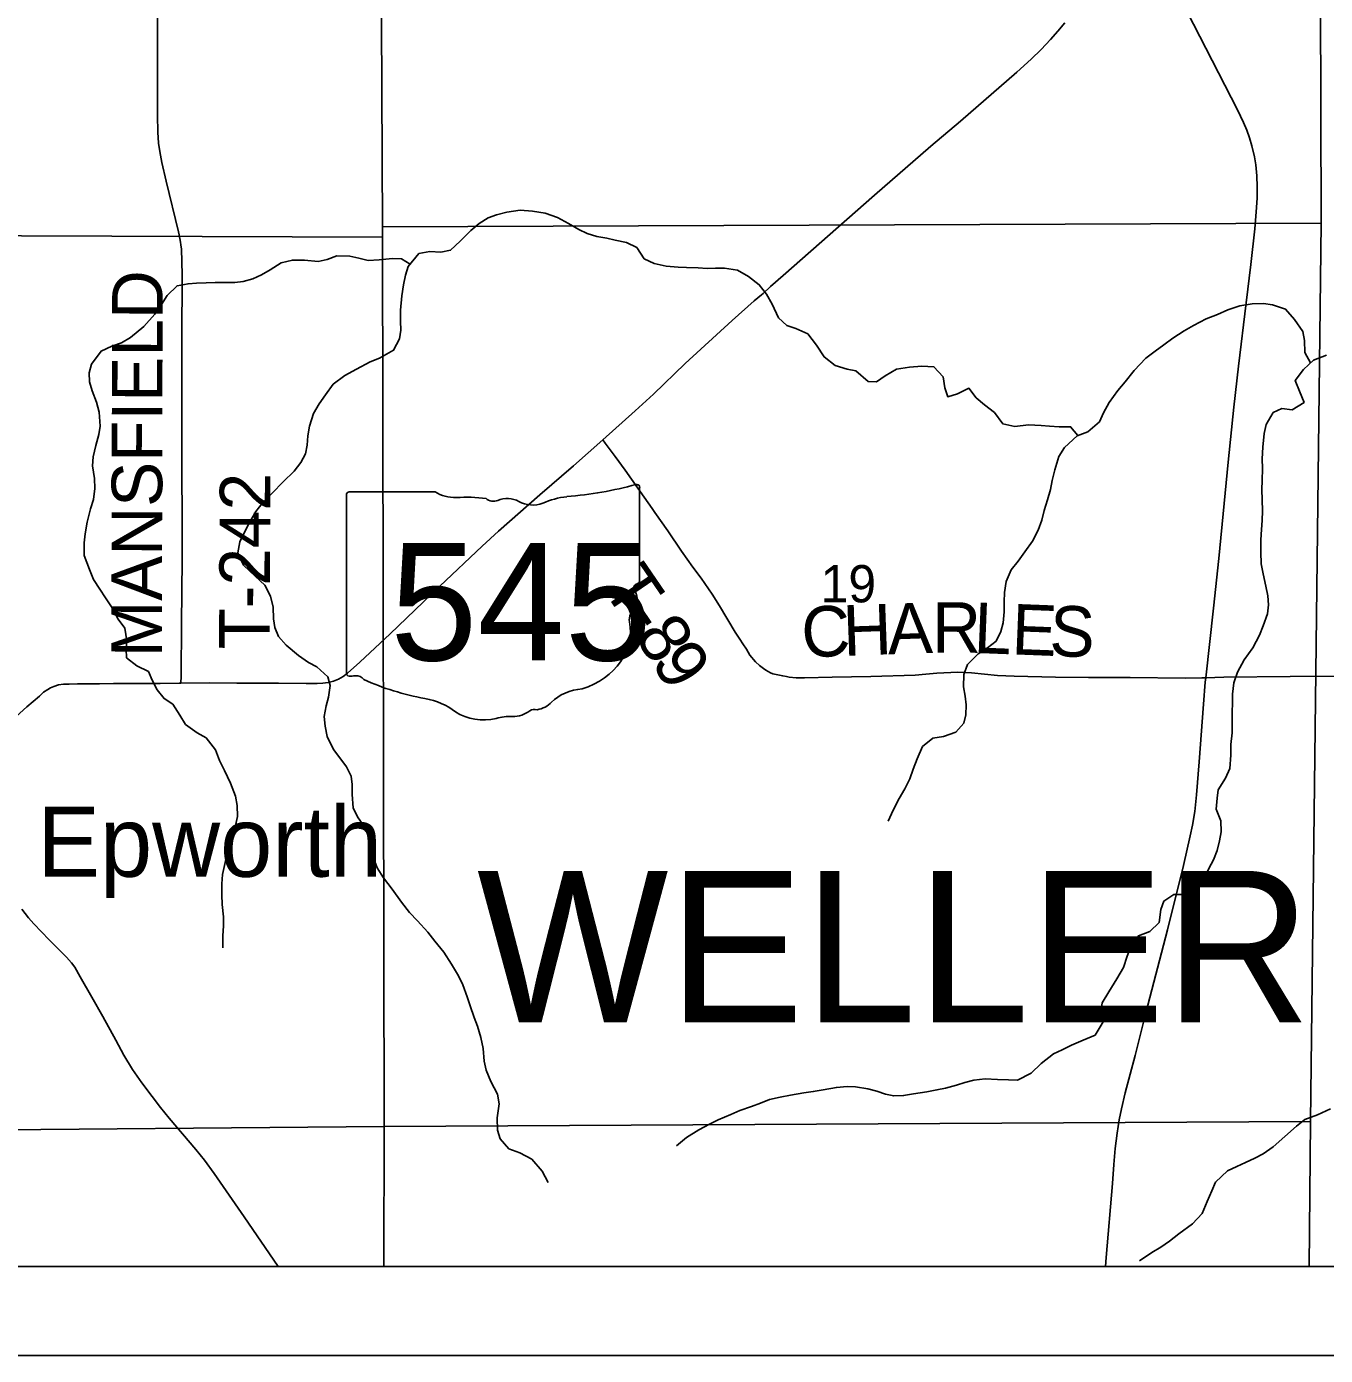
# Model space of a CAD drawing. Extents: x 0 to 34, y 0 to 22.
# Drawn here: x 5.038 to 6.497, y 14 to 15.494 of the extents above; entities that cross this region are included whole.
import ezdxf

# ---------------------------------------------------------------- set-up
doc = ezdxf.new("R2010")
doc.units = 0
for name, color, linetype in [('Default', 7, 'Continuous'), ('GM_X_County_Road', 7, 'Continuous'), ('GM_X_Minor_River', 7, 'Continuous'), ('GM_X_Section', 7, 'Continuous'), ('GM_X_Section_Text', 7, 'Continuous'), ('GM_X_State_Location', 7, 'Continuous'), ('GM_X_State_Route', 7, 'Continuous'), ('GM_X_State_Shield', 7, 'Continuous'), ('GM_X_Township_Road', 7, 'Continuous'), ('GM_X_Township_Road_Text', 7, 'Continuous'), ('GM_X_Township_Text', 7, 'Continuous'), ('GM_X_Unincorporated_Text', 7, 'Continuous'), ('SH_Cut_Line', 7, 'Continuous'), ('SH_Data', 7, 'Continuous')]:
    doc.layers.add(name, color=color, linetype=linetype)

msp = doc.modelspace()

# ---------------------------------------------------------------- linework, layer by layer
at = {"layer": 'Default'}
for points in [[(4.4126, 14.1), (5.4393, 14.1), (5.4396, 14.2573), (4.4107, 14.2482)], [(5.4393, 14.1), (6.4792, 14.1), (6.4806, 14.263), (5.4396, 14.2573)]]:
    msp.add_lwpolyline(points, close=True, dxfattribs=at)
msp.add_lwpolyline([(3.4093, 14.1), (7.4893, 14.1)], dxfattribs=at)
at = {"layer": 'GM_X_County_Road'}
for points in [[(6.363, 14.7617), (6.3718, 14.8401), (6.3776, 14.8957), (6.3836, 14.9576), (6.3883, 15.0039), (6.3946, 15.0658), (6.3996, 15.1121), (6.4083, 15.183), (6.4137, 15.2261), (6.4181, 15.2664), (6.4198, 15.2853), (6.4206, 15.301), (6.4207, 15.3135), (6.4202, 15.3259), (6.4191, 15.3382), (6.4177, 15.3474), (6.4149, 15.3596), (6.4122, 15.3685), (6.4091, 15.3774), (6.4055, 15.386), (6.3988, 15.4001), (6.3846, 15.4277), (6.3348, 15.5244)], [(6.2505, 14.1), (6.2511, 14.1102), (6.2581, 14.1931), (6.2598, 14.2146), (6.2613, 14.2324), (6.2634, 14.2499), (6.2658, 14.2649), (6.2682, 14.277), (6.2724, 14.2951), (6.2835, 14.337), (6.2958, 14.3852), (6.3201, 14.4783), (6.3378, 14.5505), (6.3456, 14.584), (6.348, 14.5961), (6.3506, 14.6114), (6.3527, 14.63), (6.3557, 14.6671), (6.3605, 14.7321), (6.3624, 14.7568), (6.363, 14.7617)]]:
    msp.add_lwpolyline(points, dxfattribs=at)
at = {"layer": 'GM_X_Minor_River'}
for points in [[(6.2193, 15.0339), (6.211, 15.0439), (6.1981, 15.0439), (6.1875, 15.0446), (6.1781, 15.0454), (6.1637, 15.0461), (6.1485, 15.0442), (6.1348, 15.0473), (6.1254, 15.0598), (6.1144, 15.0685), (6.1049, 15.0765), (6.0969, 15.0871), (6.0841, 15.081), (6.0731, 15.0776), (6.0697, 15.0875), (6.0678, 15.1), (6.0575, 15.1114), (6.0439, 15.1121), (6.0299, 15.111), (6.0155, 15.1087), (6.0026, 15.1011), (5.9931, 15.0943), (5.9836, 15.0947), (5.9696, 15.1068), (5.9601, 15.1087), (5.9465, 15.1129), (5.934, 15.1224), (5.9256, 15.1356), (5.9158, 15.1485), (5.9025, 15.1542), (5.8923, 15.1576), (5.8828, 15.1664), (5.8756, 15.1815), (5.8692, 15.1929), (5.8612, 15.2035), (5.8491, 15.2126), (5.8366, 15.2198), (5.8222, 15.2221), (5.8119, 15.2221), (5.8025, 15.2217), (5.7926, 15.2225), (5.7793, 15.2229), (5.7699, 15.2232), (5.7566, 15.2244), (5.7433, 15.2274), (5.7319, 15.2327), (5.7236, 15.2452), (5.7119, 15.2509), (5.6994, 15.2536), (5.6899, 15.2558), (5.6785, 15.2577), (5.6679, 15.2612), (5.6584, 15.2657), (5.647, 15.2725), (5.6345, 15.279), (5.6205, 15.2839), (5.6065, 15.2862), (5.5925, 15.2873), (5.5777, 15.285), (5.5659, 15.282), (5.5565, 15.2786), (5.5466, 15.2725), (5.5371, 15.2646), (5.525, 15.2524), (5.5144, 15.2422), (5.5034, 15.2403), (5.4912, 15.241), (5.4787, 15.2388), (5.4666, 15.224), (5.4635, 15.2141), (5.4613, 15.2035), (5.4594, 15.191), (5.4582, 15.175), (5.4582, 15.1625), (5.4586, 15.1523), (5.4571, 15.1428), (5.4502, 15.1299), (5.4343, 15.1208), (5.4241, 15.117), (5.4085, 15.1086), (5.3956, 15.1014), (5.3824, 15.0916), (5.3736, 15.0798), (5.3668, 15.0696), (5.3603, 15.0586), (5.3558, 15.0445), (5.3539, 15.0335), (5.3531, 15.0233), (5.3512, 15.0134), (5.3459, 15.0036), (5.3387, 14.9941), (5.3262, 14.982), (5.3137, 14.9694), (5.3038, 14.9592), (5.2955, 14.9486), (5.2883, 14.9364), (5.2822, 14.9247), (5.2776, 14.9144), (5.2754, 14.9023), (5.2818, 14.8883), (5.2947, 14.8761)], [(5.4689, 15.2268), (5.459, 15.2327), (5.4491, 15.2331), (5.434, 15.2315), (5.4218, 15.2308), (5.4112, 15.2334), (5.401, 15.2357), (5.3866, 15.2361), (5.3756, 15.2319), (5.3654, 15.2296), (5.3502, 15.2312), (5.3366, 15.2312), (5.324, 15.2281), (5.3115, 15.2201), (5.3017, 15.2145), (5.2922, 15.2103), (5.2812, 15.2072), (5.2717, 15.2061), (5.2497, 15.2061), (5.2395, 15.2057), (5.2289, 15.2053), (5.2194, 15.2046), (5.2069, 15.2023), (5.1959, 15.1913), (5.1894, 15.1814), (5.1819, 15.1704), (5.1697, 15.1564), (5.1546, 15.1443), (5.1447, 15.1382), (5.1337, 15.1344), (5.1216, 15.1287), (5.1109, 15.1143), (5.1083, 15.1044), (5.1087, 15.0942), (5.1117, 15.0843), (5.1166, 15.0714), (5.1193, 15.0604), (5.1204, 15.0445), (5.1192, 15.035), (5.1158, 15.0229), (5.1128, 15.01), (5.112, 14.9998), (5.1143, 14.9857), (5.1147, 14.9743), (5.1131, 14.9622), (5.1097, 14.9516), (5.1059, 14.9368), (5.1036, 14.9235), (5.1025, 14.9133), (5.1025, 14.8992), (5.1085, 14.8833), (5.1131, 14.8723), (5.1203, 14.8613), (5.1267, 14.8514), (5.1347, 14.8393), (5.1407, 14.8276), (5.1483, 14.8173), (5.1506, 14.8033), (5.1498, 14.7938), (5.1502, 14.7843), (5.1619, 14.7752), (5.1748, 14.7688), (5.179, 14.7589), (5.1847, 14.7483), (5.1923, 14.7384), (5.2021, 14.732), (5.2101, 14.7198), (5.2165, 14.7092), (5.2294, 14.6997), (5.2396, 14.6941), (5.2502, 14.6808), (5.2548, 14.6686), (5.2601, 14.6573), (5.2669, 14.6432), (5.2726, 14.6288), (5.2745, 14.6182), (5.2748, 14.6057), (5.2725, 14.5958), (5.2699, 14.586), (5.2665, 14.5765), (5.2638, 14.5662), (5.2604, 14.5507), (5.2581, 14.5404), (5.2573, 14.5302), (5.2573, 14.5177), (5.2577, 14.5067), (5.2592, 14.493), (5.2592, 14.4828), (5.2585, 14.4718), (5.2584, 14.4581)], [(6.4807, 15.1156), (6.4742, 15.1273), (6.4738, 15.141), (6.4719, 15.1509), (6.4628, 15.1645), (6.4526, 15.1759), (6.4378, 15.1808), (6.428, 15.1823), (6.4151, 15.1819), (6.4014, 15.1797), (6.3878, 15.1755), (6.376, 15.1702), (6.3635, 15.1653), (6.3491, 15.1577), (6.3389, 15.1516), (6.326, 15.1436), (6.3157, 15.136), (6.3062, 15.1288), (6.2956, 15.1209), (6.2827, 15.1072), (6.2725, 15.0943), (6.2641, 15.0848), (6.2543, 15.0712), (6.2482, 15.0594), (6.2436, 15.0496), (6.2304, 15.0382), (6.2186, 15.0336), (6.2042, 15.0204), (6.1978, 15.0105), (6.1932, 14.9953), (6.1905, 14.9836), (6.1886, 14.9733), (6.1852, 14.9616), (6.1814, 14.9498), (6.1788, 14.9388), (6.1746, 14.9278), (6.1681, 14.9153), (6.1598, 14.9031), (6.1522, 14.8929), (6.1442, 14.883), (6.1385, 14.8698), (6.137, 14.8576), (6.1363, 14.847), (6.1366, 14.836), (6.1355, 14.8235), (6.1328, 14.8136), (6.1275, 14.803), (6.1176, 14.7954), (6.1074, 14.7886), (6.0953, 14.7768), (6.0911, 14.7655), (6.0907, 14.7514), (6.0926, 14.7412), (6.0937, 14.7313), (6.0933, 14.7199), (6.0911, 14.7105), (6.082, 14.7006), (6.0683, 14.6957), (6.0562, 14.6938), (6.0448, 14.6843), (6.0387, 14.6706), (6.0342, 14.6589), (6.0304, 14.6482), (6.0247, 14.6369), (6.0186, 14.6259), (6.0118, 14.613), (6.0061, 14.6005)], [(6.4985, 15.1243), (6.484, 15.1186), (6.4727, 15.1084), (6.4636, 15.0959), (6.4685, 15.0837), (6.4734, 15.0712), (6.4601, 15.0629), (6.4484, 15.0644), (6.4389, 15.0598), (6.4309, 15.0465), (6.4286, 15.0363), (6.4271, 15.0211), (6.4264, 15.0079), (6.4267, 14.9969), (6.4263, 14.9836), (6.426, 14.9733), (6.4263, 14.9616), (6.4267, 14.9494), (6.4263, 14.9384), (6.4256, 14.9282), (6.4248, 14.9168), (6.4248, 14.9028), (6.4252, 14.8899), (6.4274, 14.8785), (6.4305, 14.8645), (6.4327, 14.8539), (6.4335, 14.8436), (6.4323, 14.8334), (6.4274, 14.8201), (6.4232, 14.8095), (6.416, 14.7954), (6.4061, 14.7818), (6.3986, 14.7681), (6.3944, 14.756), (6.3932, 14.7431), (6.3932, 14.7332), (6.3928, 14.7234), (6.3925, 14.7131), (6.3925, 14.6999), (6.3913, 14.6866), (6.3913, 14.6748), (6.3902, 14.6597), (6.3852, 14.649), (6.3769, 14.6358), (6.3757, 14.6263), (6.3746, 14.6141), (6.3799, 14.6009), (6.3803, 14.5884), (6.3784, 14.5785), (6.3757, 14.5675), (6.3715, 14.5569), (6.3666, 14.5474), (6.359, 14.5318), (6.3503, 14.5193), (6.34, 14.5182), (6.3272, 14.5182), (6.3158, 14.5106), (6.3124, 14.5011), (6.3105, 14.4867), (6.3002, 14.4765), (6.2873, 14.4715), (6.2786, 14.4598), (6.2748, 14.4488), (6.2706, 14.4362), (6.263, 14.4233), (6.2539, 14.4086), (6.2467, 14.3964), (6.2452, 14.3866), (6.2478, 14.3748), (6.2387, 14.36), (6.2251, 14.3543), (6.2122, 14.3486), (6.2016, 14.3433), (6.1917, 14.3391), (6.1781, 14.3281), (6.1667, 14.3171), (6.1515, 14.3092), (6.1413, 14.3096), (6.1288, 14.3103), (6.1151, 14.3107), (6.1022, 14.3092), (6.0924, 14.3069), (6.0829, 14.3039), (6.0704, 14.3004), (6.0609, 14.2985), (6.0495, 14.2963), (6.0347, 14.294), (6.0234, 14.2921), (6.0124, 14.2917), (6.0029, 14.2936), (5.9934, 14.297), (5.9832, 14.2997), (5.9695, 14.3019), (5.9601, 14.3023), (5.9479, 14.3012), (5.9331, 14.2985)], [(5.2947, 14.8761), (5.3057, 14.8659), (5.3121, 14.8534), (5.3151, 14.8412), (5.3155, 14.828), (5.317, 14.8181), (5.3208, 14.8082), (5.3295, 14.7984), (5.3435, 14.7866), (5.3545, 14.779), (5.364, 14.7741), (5.3765, 14.7627), (5.3791, 14.7529), (5.3772, 14.74), (5.3746, 14.7301), (5.3723, 14.718), (5.3734, 14.7073), (5.3757, 14.6956), (5.3829, 14.6812), (5.3897, 14.6717), (5.3973, 14.6615), (5.4026, 14.6512), (5.4037, 14.6417), (5.4037, 14.6304), (5.4049, 14.6156), (5.4098, 14.6053), (5.4174, 14.5947), (5.4242, 14.5837), (5.4261, 14.5738), (5.4276, 14.5594), (5.4317, 14.5481), (5.4389, 14.5367), (5.4488, 14.5242), (5.459, 14.5094), (5.4681, 14.498), (5.4772, 14.4885), (5.4886, 14.4756), (5.4965, 14.4658), (5.5067, 14.4532), (5.5155, 14.4396), (5.5234, 14.4267), (5.528, 14.4164), (5.5329, 14.4032), (5.5363, 14.3929), (5.5408, 14.3797), (5.5446, 14.3702), (5.5484, 14.3573), (5.551, 14.3451), (5.5522, 14.3307), (5.5544, 14.3205), (5.5597, 14.308), (5.5669, 14.2936), (5.5688, 14.2829), (5.5665, 14.267), (5.5669, 14.253), (5.5699, 14.2435), (5.5798, 14.2321), (5.5923, 14.2276), (5.6056, 14.2204), (5.6173, 14.2071), (5.6241, 14.1942)], [(5.9331, 14.2985), (5.9218, 14.2966), (5.9112, 14.2951), (5.8964, 14.2925), (5.8846, 14.2902), (5.8729, 14.2875), (5.8626, 14.2834), (5.8524, 14.2799), (5.8395, 14.2754), (5.8293, 14.2708), (5.8149, 14.2648), (5.8054, 14.2598), (5.7932, 14.2534), (5.7796, 14.245), (5.7682, 14.2356)], [(6.5033, 14.2773), (6.4885, 14.2705), (6.4745, 14.2652), (6.465, 14.2576), (6.4517, 14.2462), (6.4388, 14.2345), (6.4275, 14.2265), (6.418, 14.2216), (6.4077, 14.217), (6.3979, 14.2125), (6.3876, 14.2075), (6.374, 14.1946), (6.3698, 14.1848), (6.3645, 14.173), (6.3588, 14.1594), (6.3482, 14.148), (6.3326, 14.1366), (6.3224, 14.1283), (6.3125, 14.1218), (6.3023, 14.1158), (6.2886, 14.1063)]]:
    msp.add_lwpolyline(points, dxfattribs=at)
at = {"layer": 'GM_X_Section'}
for points in [[(5.4343, 16.2844), (6.4897, 16.2833), (6.4927, 15.2726), (5.4377, 15.2688), (5.4328, 16.2708)], [(4.4273, 16.2727), (5.4328, 16.2708), (5.4377, 15.2688), (5.4377, 15.257), (4.4235, 15.2608)], [(6.4927, 15.2726), (6.4806, 14.263), (5.4396, 14.2573), (5.4377, 15.257), (5.4377, 15.2688)], [(4.4235, 15.2608), (5.4377, 15.257), (5.4396, 14.2573), (4.4107, 14.2482)]]:
    msp.add_lwpolyline(points, close=True, dxfattribs=at)
at = {"layer": 'GM_X_State_Route'}
for points in [[(6.0873, 15.3875), (6.1506, 15.4426), (6.1667, 15.4572), (6.1779, 15.4679), (6.1886, 15.4791), (6.1969, 15.4884), (6.2047, 15.498)], [(5.0058, 14.7001), (5.038, 14.7292), (5.0525, 14.7412), (5.057, 14.7456), (5.0616, 14.7486), (5.0648, 14.7503), (5.0684, 14.7519), (5.0737, 14.7536), (5.0795, 14.7545), (5.0857, 14.7547), (5.0949, 14.755), (5.1076, 14.7548), (5.1198, 14.755), (5.1357, 14.7553), (5.1879, 14.7554), (5.2094, 14.7556), (5.2113, 14.7556), (5.2435, 14.7559), (5.2743, 14.7556), (5.3209, 14.7557), (5.352, 14.7552), (5.3644, 14.7553), (5.3706, 14.7557), (5.3767, 14.7565), (5.3796, 14.7571), (5.3826, 14.758), (5.3882, 14.7602), (5.3909, 14.7616), (5.3935, 14.7632), (5.3984, 14.7668), (5.4122, 14.7793), (5.4463, 14.811), (5.5024, 14.8647), (5.5497, 14.9097), (5.5681, 14.9265), (5.6148, 14.9674), (5.6524, 14.9998), (5.6853, 15.0292), (5.7217, 15.0616), (5.7422, 15.0807), (5.7781, 15.115), (5.8306, 15.1633), (5.8556, 15.1853), (5.8639, 15.1923), (5.8657, 15.1937), (5.874, 15.2015), (5.888, 15.2138), (5.9909, 15.3041), (6.0542, 15.3593), (6.0873, 15.3875)]]:
    msp.add_lwpolyline(points, dxfattribs=at)
at = {"layer": 'GM_X_State_Shield'}
for p, q in [((5.497, 14.9706), (5.4005, 14.9706)), ((5.7268, 14.8709), (5.7268, 14.9756)), ((5.3972, 14.9672), (5.3972, 14.7671)), ((5.7268, 14.8709), (5.7268, 14.8709))]:
    msp.add_line(p, q, dxfattribs=at)
for centre, major_axis, start_param, end_param in [((5.401, 14.9676), (0.00382, 0), 1.712693, 3.28349), ((5.52, 14.9939), (0.037, 0), 4.042523, 4.731795), ((5.6094, 15.2435), (0.3495, 0), 4.814394, 5.042369), ((5.7232, 14.976), (0.00367, 0), 6.141152, 7.989035), ((5.5323, 14.8583), (0.133, 0), 1.404758, 1.657858), ((5.5625, 14.9687), (0.0107, 0), 3.836095, 5.185415), ((5.5781, 14.9455), (0.0222, 0), 0.950623, 2.079405), ((5.6068, 14.9772), (0.0267, 0), 4.081561, 5.145723), ((5.654, 14.9095), (0.0703, 0), 1.699011, 2.107814), ((5.726, 14.8632), (0.00568, 0), 1.883978, 3.671073), ((5.7229, 14.8705), (0.00393, 0), 5.05454, 6.418171), ((5.6898, 14.85), (0.0341, 0), 5.934695, 6.695948), ((5.74, 14.8271), (0.0248, 0), 2.387724, 3.262537), ((5.629, 14.8138), (0.0874, 0), 5.101752, 6.440018), ((5.401, 14.7666), (0.00385, 0), 3.00124, 4.508301), ((5.4016, 14.7871), (0.0294, 0), 4.665946, 4.897461), ((5.4076, 14.7555), (0.0106, 0), 0.519207, 1.627899), ((5.5415, 14.9353), (0.2524, 0), 4.195997, 4.488961), ((5.6659, 14.7109), (0.0479, 0), 1.647645, 2.488434), ((5.4662, 14.6772), (0.079, 0), 0.823519, 1.323587), ((5.6052, 14.7477), (0.0282, 0), 4.937069, 5.64225), ((5.5516, 14.7545), (0.0501, 0), 4.026481, 4.996735), ((5.5806, 14.6853), (0.0412, 0), 1.495662, 1.94098), ((5.5842, 14.7395), (0.0267, 0), 4.691044, 5.507374), ((5.6084, 14.7202), (0.00752, 0), 1.147584, 2.315152)]:
    msp.add_ellipse(centre, major_axis=major_axis, ratio=0.8, start_param=start_param, end_param=end_param, dxfattribs=at)
at = {"layer": 'GM_X_Township_Road'}
for points in [[(5.2113, 14.7556), (5.2114, 14.7637), (5.212, 14.8227), (5.2126, 14.8942), (5.2128, 14.9439), (5.2125, 14.9905), (5.2122, 15.0651), (5.2122, 15.1428), (5.2126, 15.2143), (5.2124, 15.2298), (5.2119, 15.2434), (5.2113, 15.2482), (5.211, 15.2515), (5.2094, 15.2597), (5.2087, 15.263), (5.1948, 15.3198), (5.1899, 15.341), (5.1875, 15.3533), (5.1862, 15.3626), (5.1853, 15.375), (5.1848, 15.3937), (5.1849, 15.5129)], [(5.6853, 15.0292), (5.6881, 15.0254), (5.6993, 15.0103), (5.7104, 14.9952), (5.7317, 14.9647), (5.7407, 14.9519), (5.744, 14.9474), (5.7583, 14.927), (5.774, 14.9042), (5.7867, 14.8861), (5.796, 14.8737), (5.8083, 14.8557), (5.8167, 14.8426), (5.8341, 14.813), (5.8393, 14.8051), (5.8426, 14.8), (5.8467, 14.7937), (5.8508, 14.7873), (5.8571, 14.7797), (5.8615, 14.7756), (5.8661, 14.7721), (5.8686, 14.7704), (5.8739, 14.7674), (5.8764, 14.7662), (5.882, 14.765), (5.8876, 14.7638), (5.8919, 14.763), (5.8949, 14.7624), (5.9028, 14.7618), (5.9121, 14.7618), (5.9431, 14.7623), (5.9865, 14.763), (6.0364, 14.7647), (6.0485, 14.7658), (6.0607, 14.7668), (6.0764, 14.7677), (6.0835, 14.768), (6.0996, 14.7673), (6.129, 14.7644), (6.1475, 14.7635), (6.1941, 14.7624), (6.2313, 14.7622), (6.2779, 14.7621), (6.34, 14.7614), (6.3586, 14.7615), (6.363, 14.7617)], [(6.363, 14.7617), (6.3834, 14.7625), (6.458, 14.763), (6.5356, 14.7635)], [(5.3206, 14.1), (5.2823, 14.1557), (5.2488, 14.2044), (5.2379, 14.2194), (5.2282, 14.2315), (5.198, 14.2668), (5.1884, 14.2788), (5.1789, 14.291), (5.1675, 14.3062), (5.157, 14.3215), (5.1472, 14.3375), (5.1382, 14.3542), (5.1235, 14.3811), (5.1112, 14.4025), (5.0979, 14.4257), (5.092, 14.4364), (5.0885, 14.4412), (5.0826, 14.4478), (5.0632, 14.4671), (5.046, 14.485), (5.04, 14.492), (5.0324, 14.5017)]]:
    msp.add_lwpolyline(points, dxfattribs=at)
at = {"layer": 'SH_Cut_Line'}
msp.add_lwpolyline([(2.1, 14.1), (7.4893, 14.1)], dxfattribs=at)
at = {"layer": 'SH_Data'}
for p, q in [((2.1, 14.1), (8.9, 14.1)), ((2, 14), (9, 14))]:
    msp.add_line(p, q, dxfattribs=at)

# ---------------------------------------------------------------- texts
at = {"layer": 'GM_X_Section_Text'}
msp.add_text('19', height=0.04186, rotation=0, dxfattribs=at).set_placement((5.9302, 14.8465))
at = {"layer": 'GM_X_State_Location'}
for s in ['s', 'r']:
    msp.add_text(s, height=0.000189, dxfattribs=at).set_placement((5.5583, 14.8538))
msp.add_text('545', height=0.000189, rotation=0, dxfattribs=at).set_placement((5.4915, 14.84))
at = {"layer": 'GM_X_State_Shield'}
msp.add_text('545', height=0.13184, dxfattribs=at).set_placement((5.4464, 14.7812))
at = {"layer": 'GM_X_Township_Road_Text'}
for s, height, rotation, p in [('MANSFIELD', 0.05682, 89.8806, (5.1899, 14.7849)), ('T-242', 0.05682, 89.7201, (5.3109, 14.7934)), ('T', 0.0568, 304.3414, (5.6834, 14.8632)), ('-', 0.0568, 303.9304, (5.7073, 14.8282)), ('C', 0.0568, 2.0182, (5.9095, 14.7846)), ('H', 0.0568, 2.0231, (5.9561, 14.7863)), ('A', 0.0568, 1.9967, (6.0061, 14.788)), ('R', 0.0568, 359.9336, (6.0555, 14.7898)), ('L', 0.0568, 357.7666, (6.1016, 14.7897)), ('E', 0.0568, 357.758, (6.1441, 14.7881)), ('S', 0.0568, 357.8874, (6.1867, 14.7864)), ('8', 0.0568, 302.4025, (5.7202, 14.8092)), ('9', 0.0568, 302.3463, (5.7389, 14.7796))]:
    msp.add_text(s, height=height, rotation=rotation, dxfattribs=at).set_placement(p)
at = {"layer": 'GM_X_Township_Text'}
msp.add_text('WELLER', height=0.17045, rotation=0, dxfattribs=at).set_placement((5.544, 14.3742))
at = {"layer": 'GM_X_Unincorporated_Text'}
msp.add_text('Epworth', height=0.07898, rotation=0, dxfattribs=at).set_placement((5.0498, 14.538))

doc.saveas('drawing.dxf')
